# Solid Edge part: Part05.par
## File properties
Author: Robert a Rhodes jr
Template: Normal.par
Last saved by: Rajat Kamboj
Revision: 7
Application: Solid Edge
Accuracy: 0.99
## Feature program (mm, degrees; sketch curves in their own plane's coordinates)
body "unnamed Body 1"
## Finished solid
Body 1: solid body, 82 faces, 169 edges, 90 vertices.
  Faces by surface: cylinder 44, plane 27, torus 6, spline 3, cone 2
  Edges by curve: circle 64, ellipse 44, line 26, intersection 24, curve on surface 11
Bounding box of the edges (mm; curved faces can reach further): 3403.600 x 1854.200 x 1930.410, from (-1701.8, 0, -965.2014) to (1701.8, 1854.2, 965.2088).
Cylindrical faces by radius (mm): R63.5 x26, R76.2 x4, R95.25 x4, R317.5 x4, R342.9 x3, R558.8 x1, R965.2 x2
Conical faces (half-angle, radius in mm at the cone's reference point): 15 deg R654.5026 x1, 16.46 deg R711.4955 x1
Toroidal faces (ring radius, tube radius in mm): R408.1559 r101.6 x1, R609.6 r50.8 x1, R851.7802 r50.8 x1, R889 r76.2 x2, R983.9044 r127 x1
Planar faces by outward normal: +y 20, +z 1, -y 5, -z 1
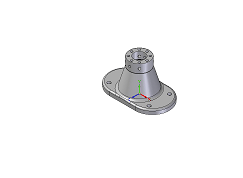
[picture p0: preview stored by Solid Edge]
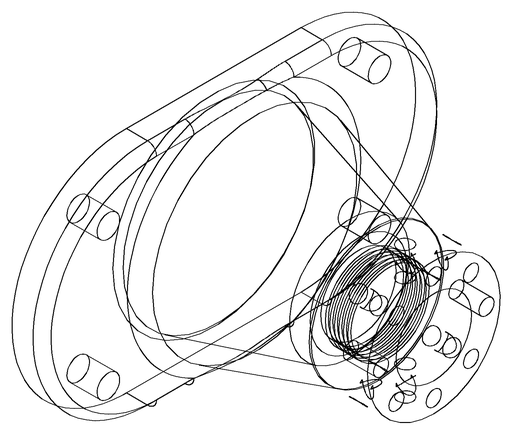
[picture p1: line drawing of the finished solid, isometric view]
